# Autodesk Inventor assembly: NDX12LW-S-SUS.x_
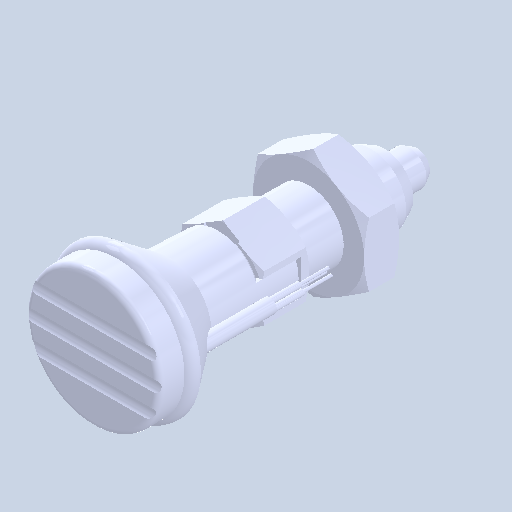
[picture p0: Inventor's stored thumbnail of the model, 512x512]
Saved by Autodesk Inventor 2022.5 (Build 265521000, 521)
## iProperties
Created: 2024-05
Part Number: NDX12LW-S-SUS.x_
Document SubType Name: Assembly
Designer: ImaoCorp
Author: ImaoCorp
Sending System: SOLIDWORKS 2022-2022290
MC: AMD64
MC_MODEL: Intel64 Family 6 Model 60 Stepping 3, GenuineIntel
OS: Windows_NT
FRU: Parasolid Version 33.1, build 260,  4-25-2022
FORMAT: text
GUISE: transmit
KEY: FILENDX12LW-S-SUS.x_t
DATE: Tue May 21 08:47:55 2024
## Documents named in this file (3)
- X:\14_SW2022-Inv2022\保留中\kipp\KME_データ\n\ndx12lw-s-sus\NDX12LW-S-SUS.x_.iam
- X:\14_SW2022-Inv2022\保留中\kipp\KME_データ\n\ndx12lw-s-sus\NDX12LW-S-SUS_01.ipt
- X:\14_SW2022-Inv2022\保留中\kipp\KME_データ\n\ndx12lw-s-sus\NDX12LW-S-SUS_02.ipt
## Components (2 placed, 2 different names)
1. NDX12LW-S-SUS_01
2. NDX12LW-S-SUS_02
